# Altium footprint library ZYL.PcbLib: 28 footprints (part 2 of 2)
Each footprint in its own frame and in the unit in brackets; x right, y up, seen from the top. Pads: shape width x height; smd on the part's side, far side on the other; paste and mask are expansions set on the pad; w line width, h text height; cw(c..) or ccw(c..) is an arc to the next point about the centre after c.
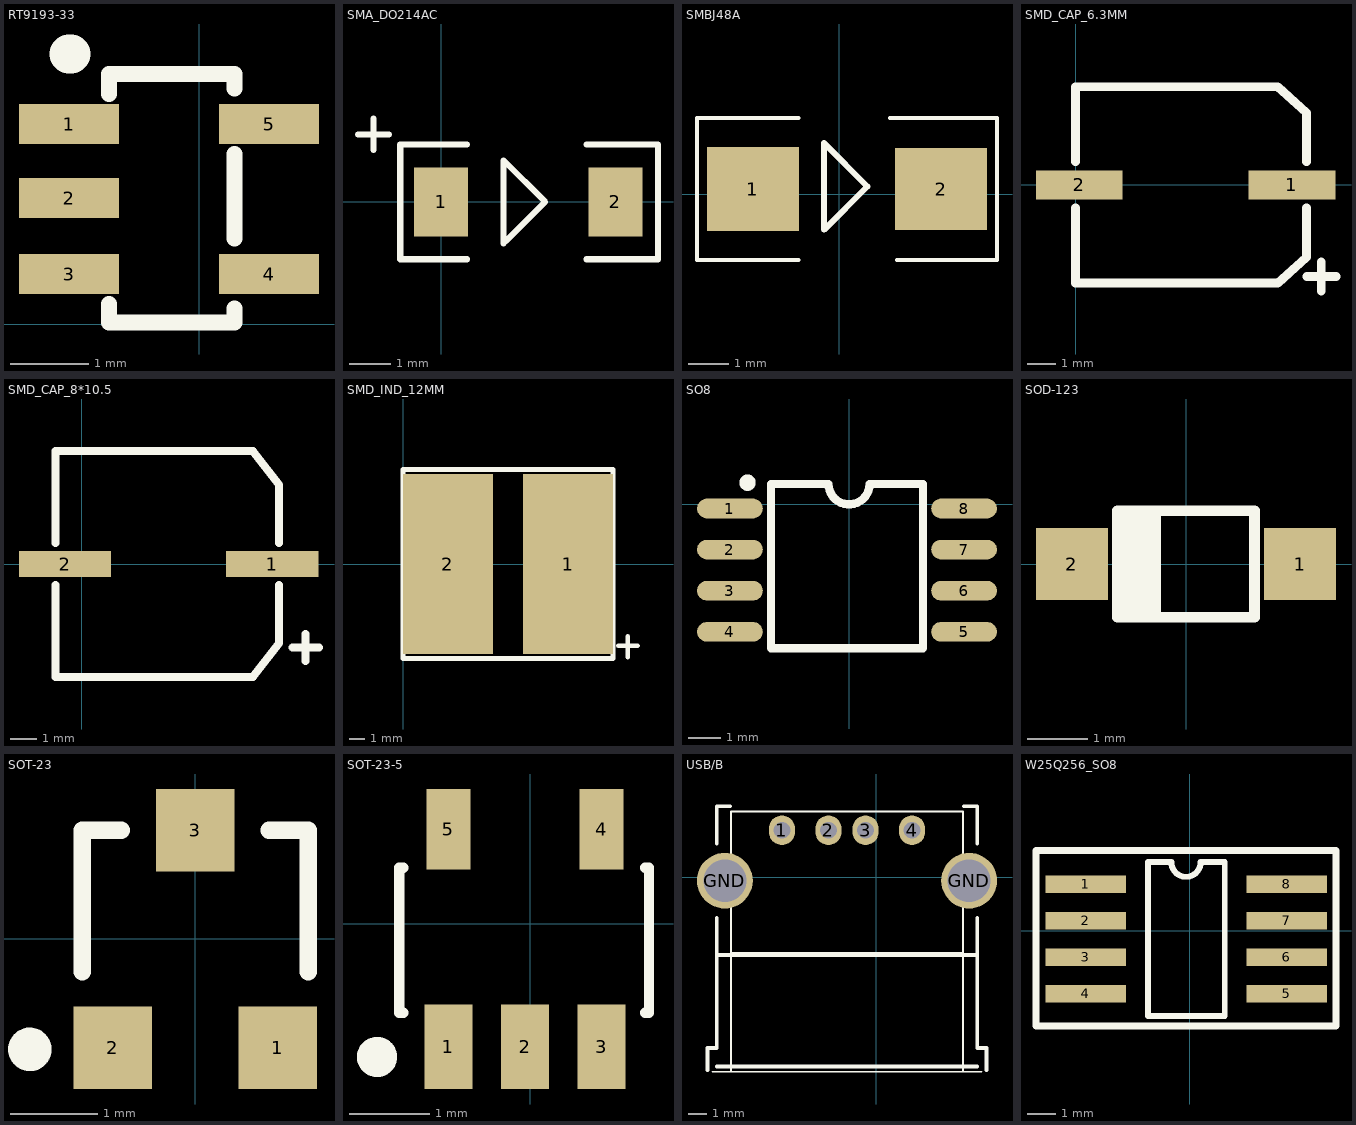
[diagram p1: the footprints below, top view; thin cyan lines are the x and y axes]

## RT9193-33 [mil]
pads (5):
  rect 50x20 smd: 1(-65,100) 2(-65,63) 3(-65,25) 4(35,25) 5(35,100)
Top Overlay:
  lines w8: -45,10 -45,0.68 17.76,0.68 17.76,7.76 ; -45,115 -45,125 17.76,125 17.76,117.76 ; 17.76,42.76 17.76,85
  lines w19.68: -65,135 -64,135

## SMA_DO214AC [mm]
pads (2):
  rect 1.32x1.68 smd: 1(0,0) 2(4.26,0)
Top Overlay:
  lines w0.15: -2.032,1.651 -1.27,1.651 ; -1.651,1.27 -1.651,2.032 ; 0.635,-1.4 -1,-1.4 -1,1.4 0.635,1.4 ; 1.524,-1.016 1.524,1.016 2.54,0 1.587,-0.953 ; 3.556,-1.4 5.3,-1.4 5.3,1.4 3.556,1.4

## SMBJ48A [mil]
pads (2):
  rect 90.55x82.99 smd: 1(-85,5)
  rect 90.55x80.99 smd: 2(100,5)
Top Overlay:
  lines w3.94: -140,-65 -140,75 ; -138.43,-65 -40,-65 ; -138.43,75 -40,75 ; 50,75 155,75 155,-65 56.57,-65
  lines w5.91: -15,-35 -15,50 27.5,7.5 -15,-35

## SMD_CAP_6.3MM [mm]
pads (2):
  rect 3x1 smd: 1(7.493,0) 2(0.127,0)
Top Overlay:
  lines w0.305: 0,-0.8 0,-3.4 7,-3.4 8,-2.5 8,-0.8 ; 0,0.8 0,3.4 7,3.4 8,2.5 8,0.8 ; 8.001,-3.175 9.017,-3.175 ; 8.509,-3.683 8.509,-2.667

## SMD_CAP_8*10.5 [mm]
pads (2):
  rect 3.5x1 smd: 1(7.239,0) 2(-0.635,0)
Top Overlay:
  lines w0.305: -1,-0.8 -1,-4.3 6.5,-4.3 7.5,-3 7.5,-0.8 ; -1,0.8 -1,4.3 6.5,4.3 7.5,3 7.5,0.8 ; 8.001,-3.175 9.017,-3.175 ; 8.509,-3.683 8.509,-2.667

## SMD_IND_12MM [mm]
pads (2):
  rect 6x12 smd: 1(11,0) 2(3,0)
Top Overlay:
  lines w0.305: 14.351,-5.461 15.632,-5.461 ; 14.986,-6.223 14.986,-4.826 ; 0,-6.3 0,6.3 14,6.3 14,-6.3 0,-6.3

## SO8 [mil]
pads (8):
  oval 80x24 smd: 1(-145,-5) 2(-145,-55) 3(-145,-105) 4(-145,-155) 5(140,-155) 6(140,-105) 7(140,-55) 8(140,-5)
Top Overlay:
  lines w10: -120,30 ccw(c-123.54,26.46) -119.06,28.7 ; -95,-175 -95,25 -25,25 ccw(c0,25) 25,25 90,25 90,-175 -95,-175

## SOD-123 [mm]
pads (2):
  rect 1.2x1.2 smd: 1(1.905,0) 2(-1.905,0)
Top Overlay:
  rectangle: -1.143,-0.889 -0.508,0.889
  lines w0.178: -0.508,-0.889 -0.508,0.889 ; -1.143,-0.889 -1.143,0.889 1.143,0.889 1.143,0.445 1.143,-0.445 1.143,-0.889 -1.143,-0.889

## SOT-23 [mm]
pads (3):
  rect 0.9x0.95 smd: 1(0.95,-1.25) 2(-0.95,-1.25) 3(0,1.25)
Top Overlay:
  circle w0.25: c-1.903,-1.27 r0.125
  lines w0.2: -1.3,-0.375 -1.3,1.25 -0.85,1.25 ; 0.85,1.25 1.3,1.25 1.3,-0.375

## SOT-23-5 [mm]
pads (5):
  rect 0.6x1.05 smd: 1(-1.016,-1.524) 2(-0.066,-1.524) 3(0.884,-1.524)
  rect 0.55x1 smd: 4(0.884,1.176) 5(-1.016,1.176)
Top Overlay:
  circle w0.25: c-1.903,-1.651 r0.125
  lines w0.127: -1.576,-1.103 -1.626,-1.103 -1.626,0.697 -1.576,0.697 ; 1.424,-1.103 1.474,-1.103 1.474,0.697 1.424,0.697
3D body: height 1.09, standoff -0.01, extent -1.502,-1.527 1.397,1.273

## USB/B [mm]
pads (6):
  oval 1.4x1.6 hole 0.9: 1(-5.08,2.54) 2(-2.58,2.54) 3(-0.58,2.54) 4(1.92,2.54)
  round 3 hole 2.3: GND(-8.15,-0.17) GND(4.99,-0.17)
Top Overlay:
  lines w0.1: -8.83,-10.45 5.67,-10.45 ; -7.83,-10.45 -7.83,3.54 4.67,3.54 4.67,-10.45 ; -7.83,-4.05 4.67,-4.05
  lines w0.2: -9.08,-10.37 -9.08,-9.17 -8.58,-9.17 -8.58,-2.17 ; -8.58,-10.17 5.42,-10.17 ; -8.58,-4.17 5.42,-4.17 ; -8.58,1.83 -8.58,3.83 -7.88,3.83 ; 4.72,3.83 5.42,3.83 5.42,1.83 ; 5.42,-2.17 5.42,-9.17 5.92,-9.17 5.92,-10.37

## W25Q256_SO8 [mil]
pads (8):
  rect 110x24 smd: 1(-142,64) 2(-142,14) 3(-142,-36) 4(-142,-86) 5(133,-86) 6(133,-36) 7(133,14) 8(133,64)
Top Overlay:
  lines w8: -57,-116 -57,94 -25,94 ccw(c-5,94) 15,94 48,94 48,-116 -57,-116
  lines w10: -210,-130 -210,110 200,110 200,-130 -210,-130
